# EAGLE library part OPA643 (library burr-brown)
Operational Amplifier
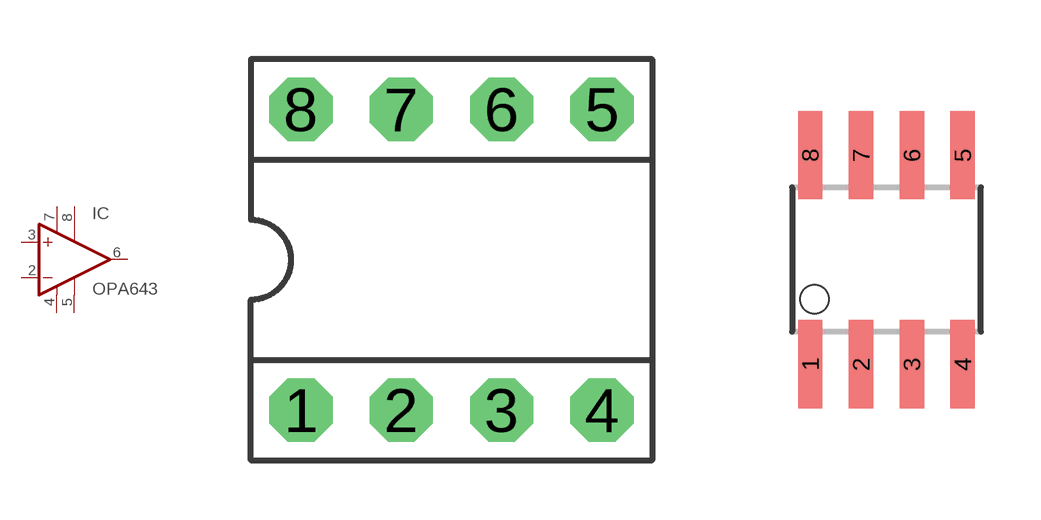
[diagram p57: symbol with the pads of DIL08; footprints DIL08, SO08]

Designator prefix IC

## OPA643P (OC_FARNELL: unknown; OC_NEWARK: unknown)  [DIL08]
2  -IN  in
3  +IN  in
4  -VS1  pwr
5  -VS2  pwr
6  OUT  out
7  +VS1  pwr
8  +VS2  pwr

## OPA643U (MF: TEXAS INSTRUMENTS; MPN: OPA643UB; OC_FARNELL: unknown; OC_NEWARK: 75C5127)  [SO08]
Pads as for DIL08

## Footprint DIL08 (pad centres in mm)
Dual In Line
drill 0.813 pad 1.6 octagon: 1 -3.81,-3.81; 2 -1.27,-3.81; 3 1.27,-3.81; 4 3.81,-3.81; 5 3.81,3.81; 6 1.27,3.81; 7 -1.27,3.81; 8 -3.81,3.81

## Footprint SO08 (pad centres in mm)
Small Outline Package
smd 0.61 x 2.21: 1 -1.905,-2.616; 2 -0.635,-2.616; 3 0.635,-2.616; 4 1.905,-2.616; 5 1.905,2.616; 6 0.635,2.616; 7 -0.635,2.616; 8 -1.905,2.616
